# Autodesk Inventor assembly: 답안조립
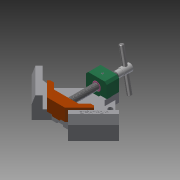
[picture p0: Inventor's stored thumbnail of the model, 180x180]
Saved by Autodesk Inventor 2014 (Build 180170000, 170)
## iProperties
Created: 2020-05
Part Number: 답안조립
Document SubType Name: Assembly
Designer: kh
Author: kh
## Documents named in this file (11)
- C:\Users\kh\Desktop\700506V1047\답안조립.iam
- C:\Users\kh\Desktop\700506V1047\본체.ipt
- C:\Users\kh\Desktop\700506V1047\리드스크류.ipt
- C:\Users\kh\Desktop\700506V1047\멈춤나사 M4x5.ipt
- C:\Users\kh\Desktop\700506V1047\멈춤나사 M4x10.ipt
- C:\Users\kh\Desktop\700506V1047\볼트 M4x16.ipt
- C:\Users\kh\Desktop\700506V1047\부시.ipt
- C:\Users\kh\Desktop\700506V1047\서포트.ipt
- C:\Users\kh\Desktop\700506V1047\조.ipt
- C:\Users\kh\Desktop\700506V1047\평행 핀 2.5x24.ipt
- C:\Users\kh\Desktop\700506V1047\핸들.ipt
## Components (1 placed, 1 different names)
1. 핸들:1
